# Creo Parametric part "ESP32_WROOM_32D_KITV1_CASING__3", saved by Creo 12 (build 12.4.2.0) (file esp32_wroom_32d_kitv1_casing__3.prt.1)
Units: Custom; MM, KILOGRAM, SECS

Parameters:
  PTC_WM_ITERATION = "0"
  PTC_WM_VERSION = "-.0"
  PTC_WM_LIFECYCLE_STATE = "In Work"
  PTC_WM_LIFECYCLE = "MO_CADDocument"
  PTC_WM_CREATED_BY = "Maximilian Roepper (Z0017RMS: MO)"
  PTC_WM_CREATED_ON = "18-Sep-26 11:36:42 AM"
  PTC_WM_MODIFIED_BY = "Maximilian Roepper (Z0017RMS: MO)"
  PTC_WM_MODIFIED_ON = "18-Sep-26 11:36:46 AM"
  PDMLINKNUMBER = "PDM000071455126"
  PTC_WM_NAME = "esp32_wroom_32d_kitv1_casing__3.prt"
  PTC_WM_NUMBER = "PDM000071455126"

Other parameters: WEIGHT, WEIGHT_FACTOR, WEIGHT_ADD, _MASS_TEMP, _DIFF_TEMP, MC_ERRORS, SUPPLIER

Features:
  1. coordinate system
  2. datum plane "PRT_YZ"
  3. datum plane "PRT_XY"
  4. datum plane "PRT_XZ"
  5. coordinate system
  6. datum axis
  7. datum axis
  8. datum axis
  9. coordinate system
  10. imported feature
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
Other named items: PRT, SIEMENS_MO, DRW_VIEW_ORG, PRT_X, PRT_Y, PRT_Z, CS0, ROUGH_GROB

Layers: 00_STD_CSYS-KSYS, 01_STD_PLANES-EBENEN, 02_STD_AXES-ACHSEN, 03_STD_CSYS-KSYS, 24_IMPORT_FEAT-IMPORT_KE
